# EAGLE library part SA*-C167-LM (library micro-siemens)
MICROPROCESSOR/PERIPHERAL DEVICE
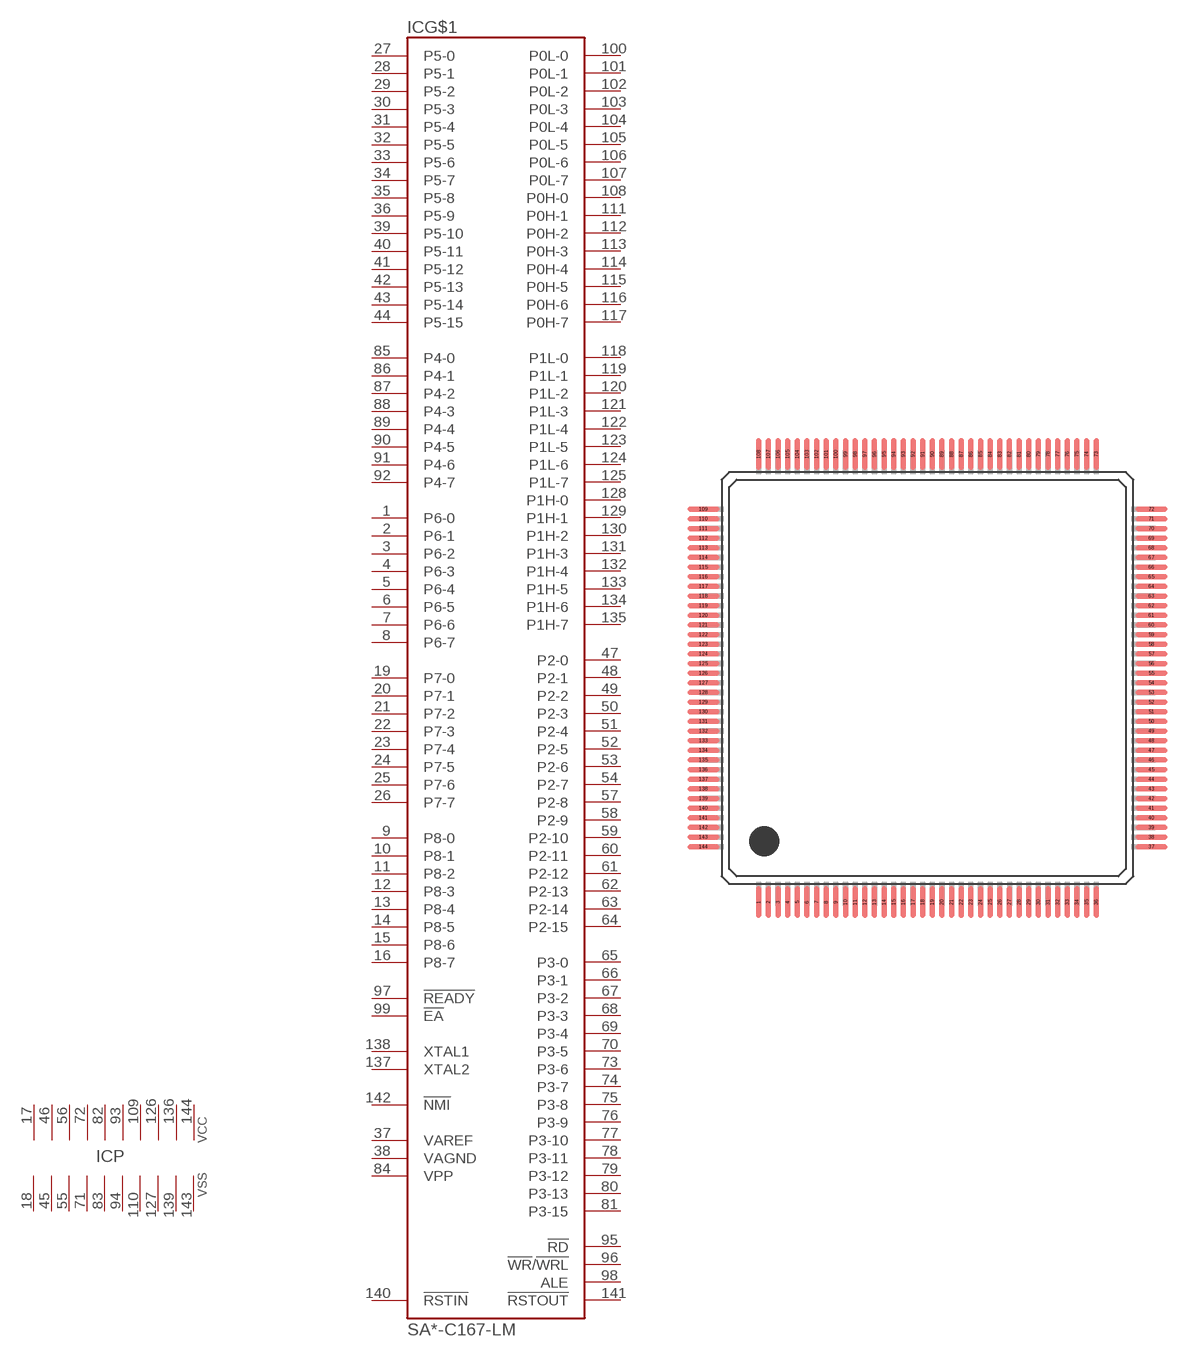
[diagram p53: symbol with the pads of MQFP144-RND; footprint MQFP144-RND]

Designator prefix IC; gates G$1=C167-1 P=10VCCVSS

## SAB-C167-LM (OC_FARNELL: unknown; OC_NEWARK: unknown), SAF-C167-LM (OC_FARNELL: unknown; OC_NEWARK: unknown), SAK-C167-LM (MPN: SAK-C167CR-LM HA; OC_FARNELL: 1220083; OC_NEWARK: 24M7191)  [MQFP144-RND]
1  G$1:P6-0
2  G$1:P6-1
3  G$1:P6-2
4  G$1:P6-3
5  G$1:P6-4
6  G$1:P6-5
7  G$1:P6-6
8  G$1:P6-7
9  G$1:P8-0
10  G$1:P8-1
11  G$1:P8-2
12  G$1:P8-3
13  G$1:P8-4
14  G$1:P8-5
15  G$1:P8-6
16  G$1:P8-7
17  P:VCC  pwr
18  P:VSS  pwr
19  G$1:P7-0
20  G$1:P7-1
21  G$1:P7-2
22  G$1:P7-3
23  G$1:P7-4
24  G$1:P7-5
25  G$1:P7-6
26  G$1:P7-7
27  G$1:P5-0  in
28  G$1:P5-1  in
29  G$1:P5-2  in
30  G$1:P5-3  in
31  G$1:P5-4  in
32  G$1:P5-5  in
33  G$1:P5-6  in
34  G$1:P5-7  in
35  G$1:P5-8  in
36  G$1:P5-9  in
37  G$1:VAREF  pas
38  G$1:VAGND  pas
39  G$1:P5-10  in
40  G$1:P5-11  in
41  G$1:P5-12  in
42  G$1:P5-13  in
43  G$1:P5-14  in
44  G$1:P5-15  in
45  P:VSS  pwr
46  P:VCC  pwr
47  G$1:P2-0
48  G$1:P2-1
49  G$1:P2-2
50  G$1:P2-3
51  G$1:P2-4
52  G$1:P2-5
53  G$1:P2-6
54  G$1:P2-7
55  P:VSS  pwr
56  P:VCC  pwr
57  G$1:P2-8
58  G$1:P2-9
59  G$1:P2-10
60  G$1:P2-11
61  G$1:P2-12
62  G$1:P2-13
63  G$1:P2-14
64  G$1:P2-15
65  G$1:P3-0
66  G$1:P3-1
67  G$1:P3-2
68  G$1:P3-3
69  G$1:P3-4
70  G$1:P3-5
71  P:VSS  pwr
72  P:VCC  pwr
73  G$1:P3-6
74  G$1:P3-7
75  G$1:P3-8
76  G$1:P3-9
77  G$1:P3-10
78  G$1:P3-11
79  G$1:P3-12
80  G$1:P3-13
81  G$1:P3-15
82  P:VCC  pwr
83  P:VSS  pwr
84  G$1:VPP  pas
85  G$1:P4-0
86  G$1:P4-1
87  G$1:P4-2
88  G$1:P4-3
89  G$1:P4-4
90  G$1:P4-5
91  G$1:P4-6
92  G$1:P4-7
93  P:VCC  pwr
94  P:VSS  pwr
95  G$1:!RD  out
96  G$1:!WR!/!WRL  out
97  G$1:!READY  in
98  G$1:ALE  out
99  G$1:!EA  in
100  G$1:P0L-0
101  G$1:P0L-1
102  G$1:P0L-2
103  G$1:P0L-3
104  G$1:P0L-4
105  G$1:P0L-5
106  G$1:P0L-6
107  G$1:P0L-7
108  G$1:P0H-0
109  P:VCC  pwr
110  P:VSS  pwr
111  G$1:P0H-1
112  G$1:P0H-2
113  G$1:P0H-3
114  G$1:P0H-4
115  G$1:P0H-5
116  G$1:P0H-6
117  G$1:P0H-7
118  G$1:P1L-0
119  G$1:P1L-1
120  G$1:P1L-2
121  G$1:P1L-3
122  G$1:P1L-4
123  G$1:P1L-5
124  G$1:P1L-6
125  G$1:P1L-7
126  P:VCC  pwr
127  P:VSS  pwr
128  G$1:P1H-0
129  G$1:P1H-1
130  G$1:P1H-2
131  G$1:P1H-3
132  G$1:P1H-4
133  G$1:P1H-5
134  G$1:P1H-6
135  G$1:P1H-7
136  P:VCC  pwr
137  G$1:XTAL2  out
138  G$1:XTAL1  in
139  P:VSS  pwr
140  G$1:!RSTIN  in
141  G$1:!RSTOUT  out
142  G$1:!NMI  in
143  P:VSS  pwr
144  P:VCC  pwr

## Footprint MQFP144-RND (pad centres in mm)
Metric Quad Flat Pack with rounded pads
smd 0.35 x 2.2: 1 -11.375,-15.1; 2 -10.725,-15.1; 3 -10.075,-15.1; 4 -9.425,-15.1; 5 -8.775,-15.1; 6 -8.125,-15.1; 7 -7.475,-15.1; 8 -6.825,-15.1; 9 -6.175,-15.1; 10 -5.525,-15.1; 11 -4.875,-15.1; 12 -4.225,-15.1; 13 -3.575,-15.1; 14 -2.925,-15.1; 15 -2.275,-15.1; 16 -1.625,-15.1; 17 -0.975,-15.1; 18 -0.325,-15.1; 19 0.325,-15.1; 20 0.975,-15.1; 21 1.625,-15.1; 22 2.275,-15.1; 23 2.925,-15.1; 24 3.575,-15.1; 25 4.225,-15.1; 26 4.875,-15.1; 27 5.525,-15.1; 28 6.175,-15.1; 29 6.825,-15.1; 30 7.475,-15.1; 31 8.125,-15.1; 32 8.775,-15.1; 33 9.425,-15.1; 34 10.075,-15.1; 35 10.725,-15.1; 36 11.375,-15.1; 73 11.375,15.1; 74 10.725,15.1; 75 10.075,15.1; 76 9.425,15.1; 77 8.775,15.1; 78 8.125,15.1; 79 7.475,15.1; 80 6.825,15.1; 81 6.175,15.1; 82 5.525,15.1; 83 4.875,15.1; 84 4.225,15.1; 85 3.575,15.1; 86 2.925,15.1; 87 2.275,15.1; 88 1.625,15.1; 89 0.975,15.1; 90 0.325,15.1; 91 -0.325,15.1; 92 -0.975,15.1; 93 -1.625,15.1; 94 -2.275,15.1; 95 -2.925,15.1; 96 -3.575,15.1; 97 -4.225,15.1; 98 -4.875,15.1; 99 -5.525,15.1; 100 -6.175,15.1; 101 -6.825,15.1; 102 -7.475,15.1; 103 -8.125,15.1; 104 -8.775,15.1; 105 -9.425,15.1; 106 -10.075,15.1; 107 -10.725,15.1; 108 -11.375,15.1
smd 2.2 x 0.35: 37 15.1,-11.375; 38 15.1,-10.725; 39 15.1,-10.075; 40 15.1,-9.425; 41 15.1,-8.775; 42 15.1,-8.125; 43 15.1,-7.475; 44 15.1,-6.825; 45 15.1,-6.175; 46 15.1,-5.525; 47 15.1,-4.875; 48 15.1,-4.225; 49 15.1,-3.575; 50 15.1,-2.925; 51 15.1,-2.275; 52 15.1,-1.625; 53 15.1,-0.975; 54 15.1,-0.325; 55 15.1,0.325; 56 15.1,0.975; 57 15.1,1.625; 58 15.1,2.275; 59 15.1,2.925; 60 15.1,3.575; 61 15.1,4.225; 62 15.1,4.875; 63 15.1,5.525; 64 15.1,6.175; 65 15.1,6.825; 66 15.1,7.475; 67 15.1,8.125; 68 15.1,8.775; 69 15.1,9.425; 70 15.1,10.075; 71 15.1,10.725; 72 15.1,11.375; 109 -15.1,11.375; 110 -15.1,10.725; 111 -15.1,10.075; 112 -15.1,9.425; 113 -15.1,8.775; 114 -15.1,8.125; 115 -15.1,7.475; 116 -15.1,6.825; 117 -15.1,6.175; 118 -15.1,5.525; 119 -15.1,4.875; 120 -15.1,4.225; 121 -15.1,3.575; 122 -15.1,2.925; 123 -15.1,2.275; 124 -15.1,1.625; 125 -15.1,0.975; 126 -15.1,0.325; 127 -15.1,-0.325; 128 -15.1,-0.975; 129 -15.1,-1.625; 130 -15.1,-2.275; 131 -15.1,-2.925; 132 -15.1,-3.575; 133 -15.1,-4.225; 134 -15.1,-4.875; 135 -15.1,-5.525; 136 -15.1,-6.175; 137 -15.1,-6.825; 138 -15.1,-7.475; 139 -15.1,-8.125; 140 -15.1,-8.775; 141 -15.1,-9.425; 142 -15.1,-10.075; 143 -15.1,-10.725; 144 -15.1,-11.375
